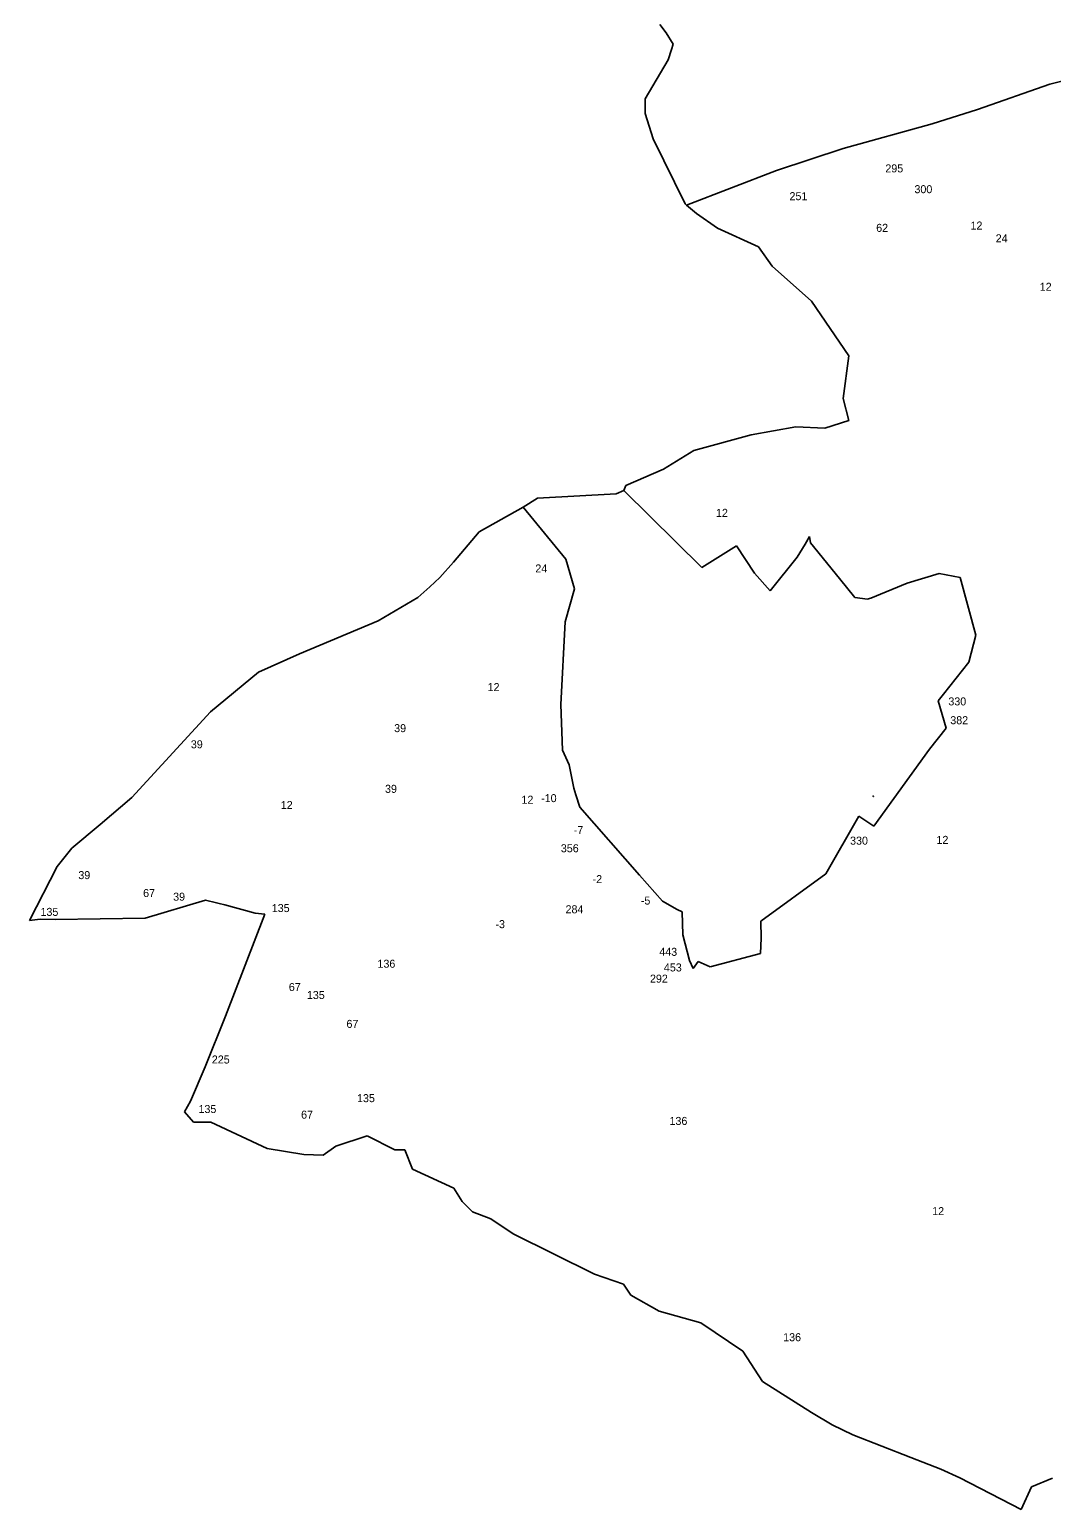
# Model space of a CAD drawing. Extents: x -782019 to -780521, y -973594 to -971888.
# Drawn here: x -782019 to -781317, y -973594 to -972577 of the extents above; entities that cross this region are included whole.
import ezdxf

# ---------------------------------------------------------------- set-up
doc = ezdxf.new("R2010")
doc.units = 0
for name, color, linetype in [('Vrstva 13', 7, 'Continuous'), ('Vrstva 24', 7, 'Continuous'), ('Vrstva 25', 7, 'Continuous')]:
    doc.layers.add(name, color=color, linetype=linetype)

msp = doc.modelspace()

# ---------------------------------------------------------------- linework, layer by layer
at = {"layer": 'Vrstva 13'}
for p, q in [((-781585.92, -972573.48), (-781581.52, -972579.28)), ((-781581.52, -972579.28), (-781576.71, -972587.04)), ((-781576.71, -972587.04), (-781577.898, -972590.558)), ((-781580.21, -972597.68), (-781596.14, -972624.52)), ((-781577.898, -972590.558), (-781580.21, -972597.68)), ((-781317.9, -972614.44), (-781294.1, -972608.5)), ((-781367.67, -972631.77), (-781317.9, -972614.44)), ((-781596.14, -972624.52), (-781595.98, -972634.6)), ((-781595.98, -972634.6), (-781590.61, -972651.96)), ((-781595.98, -972634.6), (-781595.98, -972634.6)), ((-781595.98, -972634.6), (-781595.98, -972634.6)), ((-781398.76, -972641.62), (-781367.67, -972631.77)), ((-781398.76, -972641.62), (-781459.93, -972658.68)), ((-781590.61, -972651.96), (-781568.62, -972696.7)), ((-781505.7, -972673.73), (-781459.93, -972658.68)), ((-781505.7, -972673.73), (-781567.64, -972697.68)), ((-781568.62, -972696.7), (-781567.64, -972697.68)), ((-781567.64, -972697.68), (-781560.89, -972703.25)), ((-781560.89, -972703.25), (-781546.25, -972713.42)), ((-781546.25, -972713.42), (-781518.23, -972726.16)), ((-781518.23, -972726.16), (-781508.72, -972739.48)), ((-781508.72, -972739.48), (-781481.68, -972763.63)), ((-781481.68, -972763.63), (-781456.04, -972801.1)), ((-781456.04, -972801.1), (-781459.94, -972830.54)), ((-781459.94, -972830.54), (-781456.12, -972845.6)), ((-781492.42, -972849.88), (-781523.26, -972855.53)), ((-781472.5, -972850.75), (-781492.42, -972849.88)), ((-781456.12, -972845.6), (-781472.5, -972850.75)), ((-781523.26, -972855.53), (-781562.54, -972866.2)), ((-781562.54, -972866.2), (-781583.54, -972879.03)), ((-781583.54, -972879.03), (-781609.266, -972890.22)), ((-781615.88, -972895.9), (-781610.73, -972893.69)), ((-781610.73, -972893.69), (-781609.266, -972890.22)), ((-781610.73, -972893.69), (-781557.03, -972946.6)), ((-781679.78, -972905.1), (-781669.95, -972898.86)), ((-781669.95, -972898.86), (-781615.88, -972895.9)), ((-781710.05, -972922.13), (-781679.78, -972905.1)), ((-781679.78, -972905.1), (-781650.61, -972940.85)), ((-781710.05, -972922.13), (-781727.83, -972942.97)), ((-781483.096, -972925.302), (-781486.01, -972930.61)), ((-781482.41, -972929.63), (-781483.1, -972925.3)), ((-781557.03, -972946.6), (-781533.4, -972931.71)), ((-781533.4, -972931.71), (-781520.97, -972950.52)), ((-781486.01, -972930.61), (-781491.59, -972939.49)), ((-781462.44, -972954.17), (-781482.41, -972929.63)), ((-781727.83, -972942.97), (-781737.17, -972953.47)), ((-781644.5, -972961.28), (-781650.61, -972940.85)), ((-781491.59, -972939.49), (-781510.17, -972962.69)), ((-781737.17, -972953.47), (-781743.96, -972959.96)), ((-781510.17, -972962.69), (-781520.97, -972950.52)), ((-781452, -972967.21), (-781462.44, -972954.17)), ((-781416.05, -972957.45), (-781394.07, -972950.8)), ((-781394.07, -972950.8), (-781379.58, -972953.54)), ((-781379.58, -972953.54), (-781368.82, -972993.22)), ((-781743.96, -972959.96), (-781752.35, -972967.16)), ((-781651.07, -972983.9), (-781644.5, -972961.28)), ((-781440.94, -972967.67), (-781416.05, -972957.45)), ((-781752.35, -972967.16), (-781779.48, -972983.21)), ((-781452, -972967.21), (-781443.39, -972968.26)), ((-781443.43, -972968.31), (-781440.94, -972967.67)), ((-781779.48, -972983.21), (-781833.52, -973005.9)), ((-781651.07, -972983.9), (-781653.98, -973040.82)), ((-781373.62, -973011.72), (-781368.82, -972993.22)), ((-781833.52, -973005.9), (-781861.8, -973018.64)), ((-781391, -973033.63), (-781373.62, -973011.72)), ((-781861.8, -973018.64), (-781894.63, -973045.84)), ((-781394.62, -973038.18), (-781391, -973033.63)), ((-781391, -973033.63), (-781391, -973033.63)), ((-781391, -973033.63), (-781391, -973033.63)), ((-781948.75, -973104.64), (-781894.63, -973045.84)), ((-781653.98, -973040.82), (-781652.9, -973072.2)), ((-781394.62, -973038.18), (-781389.33, -973057.06)), ((-781389.33, -973057.06), (-781400.63, -973071.55)), ((-781652.9, -973072.2), (-781648.16, -973082.14)), ((-781438.97, -973124.27), (-781400.63, -973071.55)), ((-781648.16, -973082.14), (-781644.97, -973098.19)), ((-781644.97, -973098.19), (-781643.6, -973102.75)), ((-781970.54, -973123.11), (-781948.75, -973104.64)), ((-781640.86, -973111.33), (-781643.6, -973102.75)), ((-781599.93, -973157.93), (-781640.86, -973111.33)), ((-781471.92, -973157.19), (-781449.27, -973117.57)), ((-781449.27, -973117.57), (-781438.97, -973124.27)), ((-781989.89, -973139.49), (-781970.54, -973123.11)), ((-781999.98, -973152.06), (-781989.89, -973139.49)), ((-782019, -973189.18), (-781999.98, -973152.06)), ((-781584.25, -973175.9), (-781599.93, -973157.93)), ((-781516.5, -973189.58), (-781471.92, -973157.19)), ((-781898.19, -973175.31), (-781939.62, -973187.59)), ((-781883.06, -973178.87), (-781898.19, -973175.31)), ((-781864.12, -973184.06), (-781884.96, -973178.43)), ((-781574.13, -973181.65), (-781584.25, -973175.9)), ((-782011.77, -973188.31), (-782019, -973189.18)), ((-782001.48, -973188.476), (-782011.77, -973188.31)), ((-781939.62, -973187.59), (-782001.48, -973188.476)), ((-781884.39, -973254.83), (-781857.34, -973184.89)), ((-781857.34, -973184.89), (-781864.12, -973184.06)), ((-781574.13, -973181.65), (-781570.57, -973183.24)), ((-781570.57, -973183.24), (-781570.2, -973199.15)), ((-781516.32, -973201.43), (-781516.5, -973189.58)), ((-781570.2, -973199.15), (-781565.64, -973216.62)), ((-781516.91, -973211.83), (-781516.32, -973201.43)), ((-781565.64, -973216.62), (-781563.13, -973222.09)), ((-781563.13, -973222.09), (-781559.67, -973217.26)), ((-781559.67, -973217.26), (-781551.42, -973221.13)), ((-781551.42, -973221.13), (-781516.91, -973211.83)), ((-781898.28, -973289.74), (-781884.39, -973254.83)), ((-781908.53, -973313.24), (-781898.28, -973289.74)), ((-781912.59, -973320.76), (-781908.53, -973313.24)), ((-781906.43, -973327.8), (-781912.59, -973320.76)), ((-781894.47, -973327.83), (-781906.43, -973327.8)), ((-781855.77, -973345.78), (-781894.47, -973327.83)), ((-781787.05, -973337.1), (-781808.64, -973344.22)), ((-781768.11, -973346.85), (-781787.05, -973337.1)), ((-781830.63, -973350), (-781855.77, -973345.78)), ((-781817.32, -973350.5), (-781830.63, -973350)), ((-781808.64, -973344.22), (-781817.32, -973350.5)), ((-781761.24, -973346.7), (-781768.11, -973346.85)), ((-781755.95, -973360.02), (-781761.24, -973346.7)), ((-781727.61, -973373.17), (-781755.95, -973360.02)), ((-781727.61, -973373.17), (-781721.87, -973382.27)), ((-781721.87, -973382.27), (-781714.69, -973389.37)), ((-781714.69, -973389.37), (-781702.12, -973394.11)), ((-781702.12, -973394.11), (-781686.85, -973404.48)), ((-781686.85, -973404.48), (-781630.92, -973432.31)), ((-781630.92, -973432.31), (-781611.02, -973439.17)), ((-781611.02, -973439.17), (-781605.84, -973446.56)), ((-781605.84, -973446.56), (-781586.32, -973457.58)), ((-781586.32, -973457.58), (-781557.83, -973465.72)), ((-781557.83, -973465.72), (-781528.86, -973485.11)), ((-781528.86, -973485.11), (-781515.46, -973506.02)), ((-781515.46, -973506.02), (-781481.87, -973527.18)), ((-781481.87, -973527.18), (-781467.67, -973535.72)), ((-781467.67, -973535.72), (-781453.47, -973542.63)), ((-781453.47, -973542.63), (-781413.58, -973558.27)), ((-781413.58, -973558.27), (-781392.84, -973566.31)), ((-781392.84, -973566.31), (-781379.75, -973572.22)), ((-781379.75, -973572.22), (-781337.62, -973593.87)), ((-781330.54, -973578.26), (-781316.13, -973572.32)), ((-781337.62, -973593.87), (-781330.54, -973578.26))]:
    msp.add_line(p, q, dxfattribs=at)
at = {"layer": 'Vrstva 25'}
msp.add_circle((-781439.29, -973103.78), 0.175, dxfattribs=at)

# ---------------------------------------------------------------- texts
at = {"layer": 'Vrstva 24'}
for s, p in [('295', (-781431.02, -972675.1)), ('251', (-781496.88, -972694.19)), ('300', (-781411.036, -972689.39)), ('62', (-781437.32, -972715.96)), ('12', (-781372.52, -972714.37)), ('24', (-781355.2, -972723.15)), ('12', (-781324.96, -972756.46)), ('12', (-781547.39, -972911.82)), ('24', (-781671.52, -972950.03)), ('12', (-781704.3, -973031.53)), ('330', (-781387.728, -973041.38)), ('39', (-781768.51, -973059.75)), ('382', (-781386.4, -973054.31)), ('39', (-781908.21, -973070.85)), ('39', (-781774.8, -973101.45)), ('12', (-781846.42, -973112.55)), ('12', (-781681.04, -973108.95)), ('-10', (-781667.529, -973107.85)), ('-7', (-781645.133, -973129.78)), ('356', (-781653.99, -973142.3)), ('330', (-781455.258, -973137.06)), ('12', (-781395.9, -973136.53)), ('39', (-781985.51, -973160.75)), ('-2', (-781632.152, -973163.48)), ('67', (-781941.002, -973173.08)), ('39', (-781920.38, -973175.59)), ('135', (-781852.61, -973183.39)), ('284', (-781650.76, -973184.22)), ('-5', (-781599.032, -973178.23)), ('135', (-782011.52, -973186.01)), ('-3', (-781698.932, -973194.44)), ('443', (-781586.35, -973213.46)), ('136', (-781779.989, -973221.64)), ('453', (-781583.19, -973224.2)), ('292', (-781592.75, -973231.89)), ('67', (-781840.882, -973237.64)), ('135', (-781828.48, -973243.15)), ('67', (-781801.282, -973262.99)), ('225', (-781893.8, -973287.45)), ('135', (-781794.02, -973314.02)), ('135', (-781902.96, -973321.49)), ('67', (-781832.442, -973325.35)), ('136', (-781579.339, -973329.67)), ('12', (-781398.86, -973391.66)), ('136', (-781501.219, -973478.3))]:
    msp.add_text(s, height=5.5, dxfattribs=at).set_placement(p)

doc.saveas('drawing.dxf')
